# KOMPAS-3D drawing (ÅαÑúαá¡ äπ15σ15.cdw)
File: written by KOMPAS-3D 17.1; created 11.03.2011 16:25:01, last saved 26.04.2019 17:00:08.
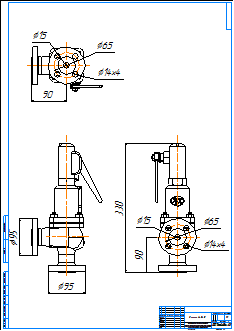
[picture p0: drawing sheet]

Sheet 1: A1, portrait

Title block, sheet 1: name: Прегран Ду15х15; material: Внимание! Данный продукт является объектом авторского права ООО «Торговый Дом АДЛ». / Запрещается изменение, копирование, распространение / (в том числе путем копирования на другие сайты и ресурсы в Интернете) / или любое иное использование информации и объектов без предварительного / согласия правообладателя (ООО «Торговый Дом АДЛ»).; scale: 1:1; sheets: 1; organisation: ООО "Торговый дом АДЛ"; sheet format: A1; stored path: C:\Users\tra\Desktop\2д чертежи\Предохранительные клапаны ПРЕГРАН\ПРЕГРАН 096\ПРЕГРАН КПП 096-03-40\KOMPAS 2D\Прегран Ду15х15.cdw

Views: Спереди 1, Проекционный вид 2, Проекционный вид 3
Dimensions and other numbers on the sheet: 95; 90; 330; 65; 14; 15; 1:1; 1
